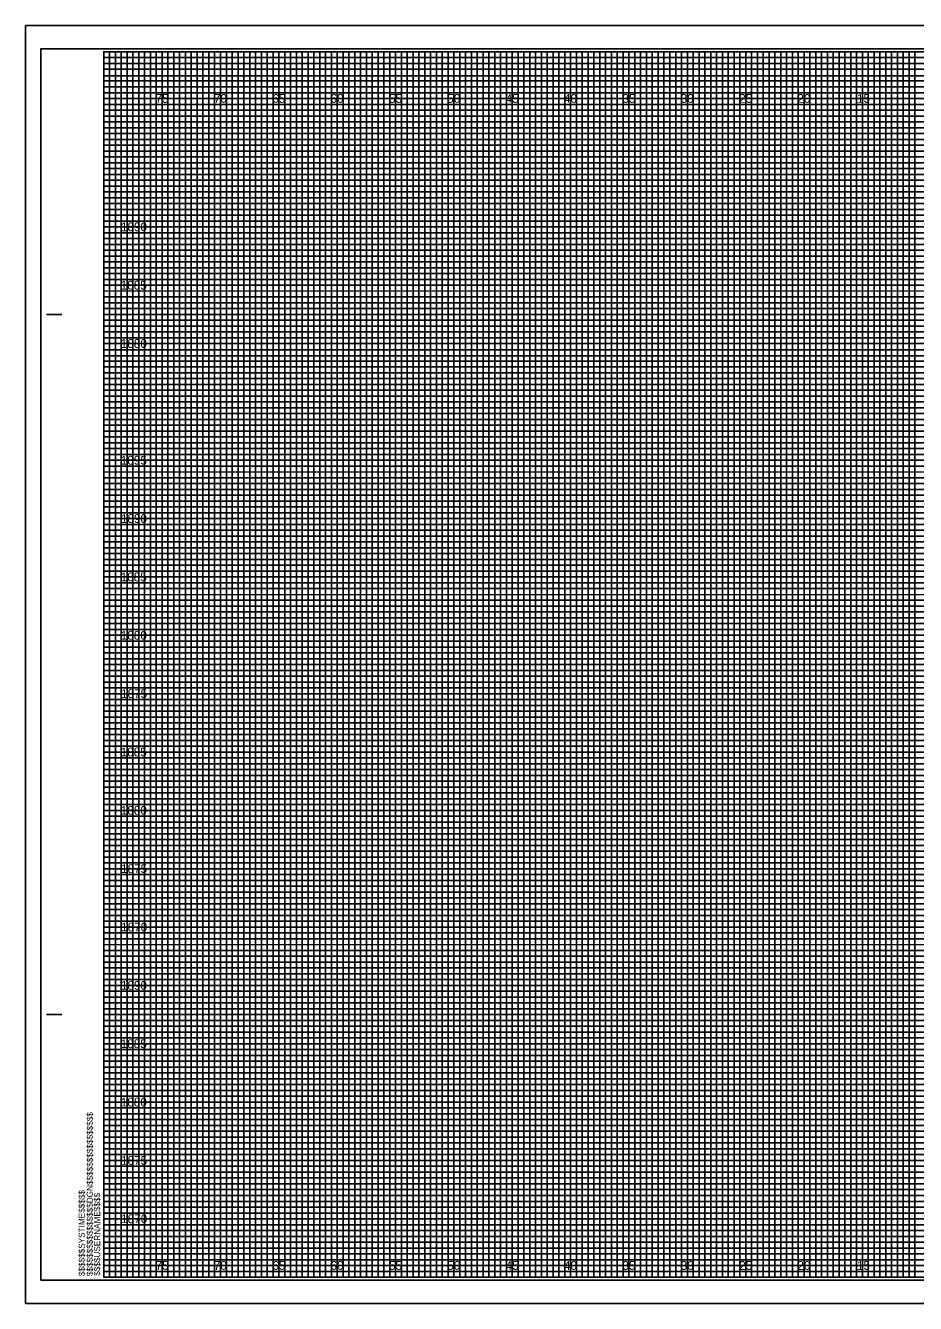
# Model space of a CAD drawing. Extents: x 3478 to 3647, y -9 to 100.
import ezdxf

# ---------------------------------------------------------------- set-up
doc = ezdxf.new("R2010")
doc.units = 0
for name, color, linetype in [('Scratch_Level_0', 7, 'Continuous'), ('Sheet Cross Section CELL', 7, 'Continuous'), ('Sheet Cross Section Grid Major CELL', 7, 'Continuous'), ('Sheet Cross Section Grid Middle CELL', 7, 'Continuous'), ('Sheet Cross Section Grid Minor 1 CELL', 7, 'Continuous'), ('Sheet Cross Section Grid Minor 2 CELL', 7, 'Continuous'), ('Sheet Cutting Line CELL', 7, 'Continuous'), ('Sheet DOT Grid CELL', 7, 'Continuous'), ('Sheet Plot Border Inside CELL', 7, 'Continuous'), ('Sheet Plot Border Outside CELL', 7, 'Continuous')]:
    doc.layers.add(name, color=color, linetype=linetype)

msp = doc.modelspace()

# ---------------------------------------------------------------- linework, layer by layer
at = {"layer": 'Sheet Cross Section CELL'}
for p, q in [((3480.11, 75.47), (3481.36, 75.47)), ((3480.16, 75.47), (3481.41, 75.47)), ((3480.11, 15.47), (3481.36, 15.47)), ((3480.16, 15.47), (3481.41, 15.47))]:
    msp.add_line(p, q, dxfattribs=at)
msp.add_lwpolyline([(3645.01, 97.97), (3485.01, 97.97), (3485.01, -7.03), (3645.01, -7.03)], close=True, dxfattribs=at)
at = {"layer": 'Sheet Cross Section Grid Major CELL'}
for p, q in [((3490.01, 97.97), (3485.01, 97.97)), ((3490.01, -7.03), (3490.01, 97.97)), ((3500.01, 97.97), (3495.01, 97.97)), ((3495.01, 97.97), (3495.01, -7.03)), ((3500.01, -7.03), (3500.01, 97.97)), ((3510.01, 97.97), (3505.01, 97.97)), ((3505.01, 97.97), (3505.01, -7.03)), ((3510.01, -7.03), (3510.01, 97.97)), ((3520.01, 97.97), (3515.01, 97.97)), ((3515.01, 97.97), (3515.01, -7.03)), ((3520.01, -7.03), (3520.01, 97.97)), ((3530.01, 97.97), (3525.01, 97.97)), ((3525.01, 97.97), (3525.01, -7.03)), ((3530.01, -7.03), (3530.01, 97.97)), ((3540.01, 97.97), (3535.01, 97.97)), ((3535.01, 97.97), (3535.01, -7.03)), ((3540.01, -7.03), (3540.01, 97.97)), ((3550.01, 97.97), (3545.01, 97.97)), ((3545.01, 97.97), (3545.01, -7.03)), ((3550.01, -7.03), (3550.01, 97.97)), ((3495.01, -7.03), (3490.01, -7.03)), ((3505.01, -7.03), (3500.01, -7.03)), ((3515.01, -7.03), (3510.01, -7.03)), ((3525.01, -7.03), (3520.01, -7.03)), ((3535.01, -7.03), (3530.01, -7.03)), ((3545.01, -7.03), (3540.01, -7.03)), ((3555.01, -7.03), (3550.01, -7.03))]:
    msp.add_line(p, q, dxfattribs=at)
for points in [[(3485.01, 92.97), (3645.01, 92.97), (3645.01, 87.97), (3485.01, 87.97)], [(3485.01, 82.97), (3645.01, 82.97), (3645.01, 77.97), (3485.01, 77.97)], [(3485.01, 72.97), (3645.01, 72.97), (3645.01, 67.97), (3485.01, 67.97)], [(3485.01, 62.97), (3645.01, 62.97), (3645.01, 57.97), (3485.01, 57.97)], [(3485.01, 52.97), (3645.01, 52.97), (3645.01, 47.97), (3485.01, 47.97)], [(3485.01, 42.97), (3645.01, 42.97), (3645.01, 37.97), (3485.01, 37.97)], [(3485.01, 32.97), (3645.01, 32.97), (3645.01, 27.97), (3485.01, 27.97)], [(3485.01, 22.97), (3645.01, 22.97), (3645.01, 17.97), (3485.01, 17.97)], [(3485.01, 12.97), (3645.01, 12.97), (3645.01, 7.97), (3485.01, 7.97)], [(3485.01, 2.97), (3645.01, 2.97), (3645.01, -2.03), (3485.01, -2.03)]]:
    msp.add_lwpolyline(points, dxfattribs=at)
at = {"layer": 'Sheet Cross Section Grid Middle CELL'}
for points in [[(3485.01, 97.97), (3487.51, 97.97), (3487.51, -7.03), (3492.51, -7.03), (3492.51, 97.97), (3497.51, 97.97), (3497.51, -7.03), (3502.51, -7.03), (3502.51, 97.97), (3507.51, 97.97), (3507.51, -7.03), (3512.51, -7.03), (3512.51, 97.97), (3517.51, 97.97), (3517.51, -7.03), (3522.51, -7.03), (3522.51, 97.97), (3527.51, 97.97), (3527.51, -7.03), (3532.51, -7.03), (3532.51, 97.97), (3537.51, 97.97), (3537.51, -7.03), (3542.51, -7.03), (3542.51, 97.97), (3547.51, 97.97), (3547.51, -7.03), (3552.51, -7.03), (3552.51, 97.97), (3557.51, 97.97)], [(3485.01, 95.47), (3622.51, 95.47)], [(3485.01, 85.47), (3645.01, 85.47), (3645.01, 90.47), (3485.01, 90.47)], [(3485.01, 75.47), (3645.01, 75.47), (3645.01, 80.47), (3485.01, 80.47)], [(3485.01, 65.47), (3645.01, 65.47), (3645.01, 70.47), (3485.01, 70.47)], [(3485.01, 55.47), (3645.01, 55.47), (3645.01, 60.47), (3485.01, 60.47)], [(3485.01, 45.47), (3645.01, 45.47), (3645.01, 50.47), (3485.01, 50.47)], [(3485.01, 35.47), (3645.01, 35.47), (3645.01, 40.47), (3485.01, 40.47)], [(3485.01, 25.47), (3645.01, 25.47), (3645.01, 30.47), (3485.01, 30.47)], [(3485.01, 15.47), (3645.01, 15.47), (3645.01, 20.47), (3485.01, 20.47)], [(3485.01, 5.47), (3645.01, 5.47), (3645.01, 10.47), (3485.01, 10.47)], [(3485.01, -4.53), (3645.01, -4.53), (3645.01, 0.47), (3485.01, 0.47)]]:
    msp.add_lwpolyline(points, dxfattribs=at)
at = {"layer": 'Sheet Cross Section Grid Minor 1 CELL'}
for p, q in [((3485.01, 97.47), (3615.01, 97.47)), ((3615.01, 96.96), (3485.01, 96.96)), ((3485.01, 96.96), (3485.01, 96.47)), ((3485.01, 96.47), (3615.01, 96.47)), ((3615.01, 95.92), (3485.01, 95.92)), ((3485.01, 95.92), (3485.01, 94.97)), ((3485.01, 94.97), (3645.01, 94.97))]:
    msp.add_line(p, q, dxfattribs=at)
for points in [[(3485.01, 94.47), (3620.01, 94.47), (3645.01, 94.47), (3645.01, 93.97), (3485.01, 93.97)], [(3485.01, 93.47), (3645.01, 93.47), (3645.01, 92.47), (3485.01, 92.47)], [(3485.01, 91.97), (3645.01, 91.97), (3645.01, 91.47), (3485.01, 91.46)], [(3485.01, 90.97), (3645.01, 90.97), (3645.01, 89.97), (3485.01, 89.97)], [(3485.01, 89.47), (3645.01, 89.47), (3645.01, 88.97), (3485.01, 88.97)], [(3485.01, 88.47), (3645.01, 88.47), (3645.01, 87.47), (3485.01, 87.47)], [(3485.01, 86.97), (3645.01, 86.97), (3645.01, 86.47), (3485.01, 86.47)], [(3485.01, 85.97), (3645.01, 85.97), (3645.01, 84.97), (3485.01, 84.97)], [(3485.01, 84.47), (3645.01, 84.47), (3645.01, 83.97), (3485.01, 83.97)], [(3485.01, 83.47), (3645.01, 83.47), (3645.01, 82.47), (3485.01, 82.47)], [(3485.01, 81.97), (3645.01, 81.97), (3645.01, 81.47), (3485.01, 81.47)], [(3485.01, 80.97), (3645.01, 80.97), (3645.01, 79.95), (3645.01, 79.47), (3645.01, 78.97), (3485.01, 78.97)], [(3485.01, 79.97), (3645.01, 79.97), (3645.01, 79.47), (3485.01, 79.47)], [(3485.01, 78.47), (3645.01, 78.47), (3645.01, 77.47), (3485.01, 77.49)], [(3485.01, 77.49), (3645.01, 77.47), (3645.01, 76.97), (3485.01, 76.97)], [(3485.01, 76.47), (3645.01, 76.47), (3645.01, 75.97), (3485.01, 75.97)], [(3485.01, 74.97), (3645.01, 74.97), (3645.01, 74.47), (3485.01, 74.47)], [(3485.01, 73.97), (3645.01, 73.97), (3645.01, 73.47), (3485.01, 73.47)], [(3484.97, 72.42), (3645.01, 72.42), (3645.01, 71.91), (3484.97, 71.91)], [(3485.01, 71.47), (3645.01, 71.47), (3645.01, 70.97), (3485.01, 70.97)], [(3485.01, 69.97), (3645.01, 69.97), (3645.01, 69.47), (3485.01, 69.47)], [(3485.01, 68.97), (3645.01, 68.97), (3645.01, 68.47), (3485.01, 68.47)], [(3485.01, 67.47), (3645.01, 67.47), (3645.01, 66.97), (3485.01, 66.97)], [(3485.01, 66.47), (3645.01, 66.47), (3645.01, 65.97), (3485.01, 65.97)], [(3485.01, 64.97), (3645.01, 64.97), (3645.01, 64.47), (3485.01, 64.47)], [(3485.01, 63.97), (3645.01, 63.97), (3645.01, 63.47), (3485.01, 63.47)], [(3485.01, 62.47), (3645.01, 62.47), (3645, 61.96), (3485.01, 61.97)], [(3485.01, 61.47), (3645.01, 61.47), (3645.01, 60.97), (3485.01, 60.97)], [(3485.01, 59.97), (3645.01, 59.97), (3645.01, 59.47), (3485.01, 59.47)], [(3485.01, 58.97), (3645.01, 58.97), (3645.01, 58.47), (3485.01, 58.47)], [(3485.01, 57.47), (3645.01, 57.47), (3645.01, 56.97), (3485.01, 56.97)], [(3485.01, 56.47), (3645.01, 56.47), (3645.01, 55.97), (3485.01, 55.97)], [(3485.01, 54.97), (3645.01, 54.97), (3645.01, 54.47), (3485.01, 54.47)], [(3485.01, 53.97), (3645.01, 53.97), (3645.01, 53.47), (3485.01, 53.47)], [(3485.01, 52.47), (3645.01, 52.47), (3645.01, 51.97), (3485.01, 51.97)], [(3485.01, 51.47), (3645.04, 51.43), (3645.01, 50.97), (3485.01, 50.97)], [(3485.01, 49.97), (3645.01, 49.97), (3645.01, 49.47), (3485.01, 49.47)], [(3485.01, 48.97), (3645.01, 48.97), (3645.01, 48.47), (3485.01, 48.47)], [(3485.01, 47.47), (3645.01, 47.47), (3645.01, 46.97), (3485.01, 46.97)], [(3485.01, 46.47), (3645.01, 46.47), (3645.01, 45.97), (3485.01, 45.97)], [(3485.01, 44.97), (3645.01, 44.97), (3645.01, 44.47), (3485.01, 44.47)], [(3485.01, 43.97), (3645.01, 43.97), (3645.01, 43.47), (3485.01, 43.47)], [(3485.01, 42.47), (3645.01, 42.47), (3645.01, 41.97), (3485.01, 41.97)], [(3485.01, 41.47), (3645.01, 41.47), (3645.01, 40.97), (3485.01, 40.97)], [(3485.01, 39.97), (3645.01, 39.97), (3645.01, 39.47), (3485.01, 39.47)], [(3485.01, 38.97), (3645.01, 38.97), (3645.01, 38.47), (3485.01, 38.47)], [(3485.01, 37.47), (3645.01, 37.47), (3645.01, 36.97), (3485.01, 36.97)], [(3485.01, 36.47), (3645.01, 36.47), (3645.01, 35.97), (3485.01, 35.97)], [(3485.01, 34.97), (3645.01, 34.97), (3645.01, 34.47), (3485.01, 34.47)], [(3485.01, 33.97), (3645.01, 33.97), (3645.01, 33.47), (3485.01, 33.47)], [(3485.01, 32.47), (3645.01, 32.47), (3645, 31.96), (3485.01, 31.97)], [(3485.01, 31.47), (3645.01, 31.47), (3645.01, 30.97), (3485.01, 30.97)], [(3485.01, 29.97), (3645.01, 29.97), (3645.01, 29.47), (3485.01, 29.47)], [(3485.01, 28.97), (3645.01, 28.97), (3645.01, 28.47), (3485.01, 28.47)], [(3485.01, 27.47), (3645.01, 27.47), (3645.01, 26.97), (3485.01, 26.97)], [(3485.01, 26.47), (3645.01, 26.47), (3645.01, 25.97), (3485.01, 25.97)], [(3485.01, 24.97), (3645.01, 24.97), (3645.01, 24.47), (3485.01, 24.47)], [(3485.01, 23.97), (3645.01, 23.97), (3645.01, 23.47), (3485.01, 23.47)], [(3485.01, 22.47), (3645.01, 22.47), (3645.01, 21.97), (3485.01, 21.97)], [(3485.01, 21.47), (3645.04, 21.43), (3645.01, 20.97), (3485.01, 20.97)], [(3485.01, 19.97), (3645.01, 19.97), (3645.01, 19.47), (3485.01, 19.47)], [(3485.01, 18.97), (3645.01, 18.97), (3645.01, 18.47), (3485.01, 18.47)], [(3485.01, 17.47), (3645.01, 17.47), (3645.01, 16.97), (3485.01, 16.97)], [(3485.01, 16.47), (3645.01, 16.47), (3645.01, 15.97), (3485.01, 15.97)], [(3485.01, 14.97), (3645.01, 14.97), (3645.01, 14.47), (3485.01, 14.47)], [(3485.01, 13.97), (3645.01, 13.97), (3645.01, 13.47), (3485.01, 13.47)], [(3485.01, 12.47), (3645.01, 12.47), (3645.01, 11.97), (3485.01, 11.97)], [(3485.01, 11.47), (3645.01, 11.47), (3645.01, 10.97), (3485.01, 10.97)], [(3485.01, 9.97), (3645.01, 9.97), (3645.01, 9.47), (3485.01, 9.47)], [(3485.01, 8.97), (3645.01, 8.97), (3645.01, 8.47), (3485.01, 8.47)], [(3485.01, 7.47), (3645.01, 7.47), (3645.01, 6.97), (3485.01, 6.97)], [(3485.01, 6.47), (3645.01, 6.47), (3645.01, 5.97), (3485.01, 5.97)], [(3485.01, 4.97), (3645.01, 4.97), (3645.01, 4.47), (3485.01, 4.47)], [(3485.01, 3.97), (3645.01, 3.97), (3645.01, 3.47), (3485.01, 3.47)], [(3485.01, 2.47), (3645.01, 2.47), (3645.01, 1.97), (3485.01, 1.97)], [(3485.01, 1.47), (3645.01, 1.47), (3645.01, 0.97), (3485.01, 0.97)], [(3485.01, -0.03), (3645.01, -0.03), (3645.01, -0.53), (3485.01, -0.53)], [(3485.01, -1.03), (3645.01, -1.03), (3645.01, -1.53), (3485.01, -1.53)], [(3485.01, -2.53), (3645.01, -2.53), (3645.01, -3.03), (3485.01, -3.03)], [(3485.01, -3.53), (3645.01, -3.53), (3645.01, -4.03), (3485.01, -4.03)], [(3485.01, -5.03), (3645.01, -5.03), (3645.01, -5.53), (3485.01, -5.53)], [(3485.01, -6.03), (3645.01, -6.03), (3645.01, -6.53), (3485.01, -6.53)]]:
    msp.add_lwpolyline(points, dxfattribs=at)
at = {"layer": 'Sheet Cross Section Grid Minor 2 CELL'}
for points in [[(3485.01, -7.03), (3485.51, -7.03), (3485.51, 97.97), (3486.01, 97.97), (3486.01, -7.03)], [(3486.01, -7.03), (3486.51, -7.03), (3486.51, 97.97), (3487.01, 97.97), (3487.01, -7.03)], [(3487.51, -7.03), (3488.01, -7.03), (3488.01, 97.97), (3488.51, 97.97), (3488.51, -7.03)], [(3488.51, -7.03), (3489.01, -7.03), (3489.01, 97.97), (3489.51, 97.97), (3489.51, -7.03)], [(3490.01, -7.03), (3490.51, -7.03), (3490.51, 97.97), (3491.01, 97.97), (3491.01, -7.03)], [(3491.01, -7.03), (3491.51, -7.03), (3491.51, 97.97), (3492.01, 97.97), (3492.01, -7.03)], [(3492.51, -7.03), (3493.01, -7.03), (3493.01, 97.97), (3493.51, 97.97), (3493.51, -7.03)], [(3493.51, -7.03), (3494.01, -7.03), (3494.01, 97.97), (3494.51, 97.97), (3494.51, -7.03)], [(3495.01, -7.03), (3495.51, -7.03), (3495.51, 97.97), (3496.01, 97.97), (3496.01, -7.03)], [(3496.01, -7.03), (3496.51, -7.03), (3496.51, 97.97), (3497.01, 97.97), (3497.01, -7.03)], [(3497.51, -7.03), (3498.01, -7.03), (3498.01, 97.97), (3498.51, 97.97), (3498.51, -7.03)], [(3498.51, -7.03), (3499.01, -7.03), (3499.01, 97.97), (3499.51, 97.97), (3499.51, -7.03)], [(3500.01, -7.03), (3500.51, -7.03), (3500.51, 97.97), (3501.01, 97.97), (3501.01, -7.03)], [(3501.01, -7.03), (3501.51, -7.03), (3501.51, 97.97), (3502.01, 97.97), (3502.01, -7.03)], [(3502.51, -7.03), (3503.01, -7.03), (3503.01, 97.97), (3503.51, 97.97), (3503.51, -7.03)], [(3503.51, -7.03), (3504.01, -7.03), (3504.01, 97.97), (3504.51, 97.97), (3504.51, -7.03)], [(3505.01, -7.03), (3505.51, -7.03), (3505.51, 97.97), (3506.01, 97.97), (3506.01, -7.03)], [(3506.01, -7.03), (3506.51, -7.03), (3506.51, 97.97), (3507.01, 97.97), (3507.01, -7.03)], [(3507.51, -7.03), (3508.01, -7.03), (3508.01, 97.97), (3508.51, 97.97), (3508.51, -7.03)], [(3508.51, -7.03), (3509.01, -7.03), (3509.01, 97.97), (3509.51, 97.97), (3509.51, -7.03)], [(3510.01, -7.03), (3510.51, -7.03), (3510.51, 97.97), (3511.01, 97.97), (3511.01, -7.03)], [(3511.01, -7.03), (3511.51, -7.03), (3511.51, 97.97), (3512.01, 97.97), (3512.01, -7.03)], [(3512.51, -7.03), (3513.01, -7.03), (3513.01, 97.97), (3513.51, 97.97), (3513.51, -7.03)], [(3513.51, -7.03), (3514.01, -7.03), (3514.01, 97.97), (3514.51, 97.97), (3514.51, -7.03)], [(3515.01, -7.03), (3515.51, -7.03), (3515.51, 97.97), (3516.01, 97.97), (3516.01, -7.03)], [(3516.01, -7.03), (3516.51, -7.03), (3516.51, 97.97), (3517.01, 97.97), (3517.01, -7.03)], [(3517.51, -7.03), (3518.01, -7.03), (3518.01, 97.97), (3518.51, 97.97), (3518.51, -7.03)], [(3518.51, -7.03), (3519.01, -7.03), (3519.01, 97.97), (3519.51, 97.97), (3519.51, -7.03)], [(3520.01, -7.03), (3520.51, -7.03), (3520.51, 97.97), (3521.01, 97.97), (3521.01, -7.03)], [(3521.01, -7.03), (3521.51, -7.03), (3521.51, 97.97), (3522.01, 97.97), (3522.01, -7.03)], [(3522.51, -7.03), (3523.01, -7.03), (3523.01, 97.97), (3523.51, 97.97), (3523.51, -7.03)], [(3523.51, -7.03), (3524.01, -7.03), (3524.01, 97.97), (3524.51, 97.97), (3524.51, -7.03)], [(3525.01, -7.03), (3525.51, -7.03), (3525.51, 97.97), (3526.01, 97.97), (3526.01, -7.03)], [(3526.01, -7.03), (3526.51, -7.03), (3526.51, 97.97), (3527.01, 97.97), (3527.01, -7.03)], [(3527.51, -7.03), (3528.01, -7.03), (3528.01, 97.97), (3528.51, 97.97), (3528.51, -7.03)], [(3528.51, -7.03), (3529.01, -7.03), (3529.01, 97.97), (3529.51, 97.97), (3529.51, -7.03)], [(3530.01, -7.03), (3530.51, -7.03), (3530.51, 97.97), (3531.01, 97.97), (3531.01, -7.03)], [(3531.01, -7.03), (3531.51, -7.03), (3531.51, 97.97), (3532.01, 97.97), (3532.01, -7.03)], [(3532.51, -7.03), (3533.01, -7.03), (3533.01, 97.97), (3533.51, 97.97), (3533.51, -7.03)], [(3533.51, -7.03), (3534.01, -7.03), (3534.01, 97.97), (3534.51, 97.97), (3534.51, -7.03)], [(3535.01, -7.03), (3535.51, -7.03), (3535.51, 97.97), (3536.01, 97.97), (3536.01, -7.03)], [(3536.01, -7.03), (3536.51, -7.03), (3536.51, 97.97), (3537.01, 97.97), (3537.01, -7.03)], [(3537.51, -7.03), (3538.01, -7.03), (3538.01, 97.97), (3538.51, 97.97), (3538.51, -7.03)], [(3538.51, -7.03), (3539.01, -7.03), (3539.01, 97.97), (3539.51, 97.97), (3539.51, -7.03)], [(3540.01, -7.03), (3540.51, -7.03), (3540.51, 97.97), (3541.01, 97.97), (3541.01, -7.03)], [(3541.01, -7.03), (3541.51, -7.03), (3541.51, 97.97), (3542.01, 97.97), (3542.01, -7.03)], [(3542.51, -7.03), (3543.01, -7.03), (3543.01, 97.97), (3543.51, 97.97), (3543.51, -7.03)], [(3543.51, -7.03), (3544.01, -7.03), (3544.01, 97.97), (3544.51, 97.97), (3544.51, -7.03)], [(3545.01, -7.03), (3545.51, -7.03), (3545.51, 97.97), (3546.01, 97.97), (3546.01, -7.03)], [(3546.01, -7.03), (3546.51, -7.03), (3546.51, 97.97), (3547.01, 97.97), (3547.01, -7.03)], [(3547.51, -7.03), (3548.01, -7.03), (3548.01, 97.97), (3548.51, 97.97), (3548.51, -7.03)], [(3548.51, -7.03), (3549.01, -7.03), (3549.01, 97.97), (3549.51, 97.97), (3549.51, -7.03)], [(3550.01, -7.03), (3550.51, -7.03), (3550.51, 97.97), (3551.01, 97.97), (3551.01, -7.03)], [(3551.01, -7.03), (3551.51, -7.03), (3551.51, 97.97), (3552.01, 97.97), (3552.01, -7.03)], [(3552.51, -7.03), (3553.01, -7.03), (3553.01, 97.97), (3553.51, 97.97), (3553.51, -7.03)], [(3553.51, -7.03), (3554.01, -7.03), (3554.01, 97.97), (3554.51, 97.97), (3554.51, -7.03)]]:
    msp.add_lwpolyline(points, dxfattribs=at)
at = {"layer": 'Sheet Cutting Line CELL'}
for p, q in [((3646.66, 100.22), (3478.31, 100.22)), ((3478.31, 100.22), (3478.31, -9.28)), ((3478.31, -9.28), (3646.66, -9.28))]:
    msp.add_line(p, q, dxfattribs=at)
at = {"layer": 'Sheet DOT Grid CELL'}
for p, q in [((3490.01, -7.03), (3490.01, 97.97)), ((3495.01, -7.03), (3495.01, 97.97)), ((3500.01, -7.03), (3500.01, 97.97)), ((3505.01, -7.03), (3505.01, 97.97)), ((3510.01, -7.03), (3510.01, 97.97)), ((3515.01, -7.03), (3515.01, 97.97)), ((3520.01, -7.03), (3520.01, 97.97)), ((3525.01, -7.03), (3525.01, 97.97)), ((3530.01, -7.03), (3530.01, 97.97)), ((3535.01, -7.03), (3535.01, 97.97)), ((3540.01, -7.03), (3540.01, 97.97)), ((3545.01, -7.03), (3545.01, 97.97)), ((3550.01, -7.03), (3550.01, 97.97)), ((3485.01, 92.97), (3645.01, 92.97)), ((3485.01, 87.97), (3645.01, 87.97)), ((3485.01, 82.97), (3645.01, 82.97)), ((3485.01, 77.97), (3645.01, 77.97)), ((3485.01, 72.97), (3645.01, 72.97)), ((3485.01, 67.97), (3645.01, 67.97)), ((3485.01, 62.97), (3645.01, 62.97)), ((3485.01, 57.97), (3645.01, 57.97)), ((3485.01, 52.97), (3645.01, 52.97)), ((3485.01, 47.97), (3645.01, 47.97)), ((3485.01, 42.97), (3645.01, 42.97)), ((3485.01, 37.97), (3645.01, 37.97)), ((3485.01, 32.97), (3645.01, 32.97)), ((3485.01, 27.97), (3645.01, 27.97)), ((3485.01, 22.97), (3645.01, 22.97)), ((3485.01, 17.97), (3645.01, 17.97)), ((3485.01, 12.97), (3645.01, 12.97)), ((3485.01, 7.97), (3645.01, 7.97)), ((3485.01, 2.97), (3645.01, 2.97)), ((3485.01, -2.03), (3645.01, -2.03))]:
    msp.add_line(p, q, dxfattribs=at)
at = {"layer": 'Sheet Plot Border Inside CELL'}
msp.add_lwpolyline([(3479.61, -7.28), (3646.21, -7.28), (3646.21, 98.22), (3479.61, 98.22)], close=True, dxfattribs=at)
at = {"layer": 'Sheet Plot Border Outside CELL'}
msp.add_lwpolyline([(3478.31, -9.28), (3646.66, -9.28), (3646.66, 100.22), (3478.31, 100.22)], close=True, dxfattribs=at)

# ---------------------------------------------------------------- texts
at = {"layer": 'Scratch_Level_0'}
for s, p in [('1890', (3486.48, 82.6)), ('1885', (3486.46, 77.6)), ('1880', (3486.47, 72.6)), ('1895', (3486.47, 62.6)), ('1890', (3486.48, 57.6)), ('1885', (3486.46, 52.6)), ('1880', (3486.47, 47.6)), ('1875', (3486.49, 42.6)), ('1885', (3486.46, 37.6)), ('1880', (3486.47, 32.6)), ('1875', (3486.49, 27.6)), ('1870', (3486.5, 22.6)), ('1890', (3486.48, 17.6)), ('1885', (3486.46, 12.6)), ('1880', (3486.47, 7.6)), ('1875', (3486.49, 2.6)), ('1870', (3486.5, -2.4))]:
    msp.add_text(s, height=0.75, dxfattribs=at).set_placement(p)
at = {"layer": 'Sheet Cross Section CELL'}
for s, p in [('$$$$$$$$$$$$$$$$DGN$$$$$$$$$$$$$$$$', (3484.07, -6.94)), ('$$$$$$SYSTIME$$$$$', (3483.38, -6.94)), ('$$$$USERNAME$$$$', (3484.7, -6.91))]:
    msp.add_text(s, height=0.525, rotation=90, dxfattribs=at).set_placement(p)
at = {"layer": 'Sheet Plot Border Outside CELL'}
for s, p in [('75', (3489.45, 93.6)), ('70', (3494.44, 93.6)), ('65', (3499.45, 93.6)), ('60', (3504.44, 93.6)), ('55', (3509.45, 93.6)), ('50', (3514.44, 93.6)), ('45', (3519.45, 93.6)), ('40', (3524.44, 93.6)), ('35', (3529.45, 93.6)), ('30', (3534.44, 93.6)), ('25', (3539.45, 93.6)), ('20', (3544.44, 93.6)), ('15', (3549.54, 93.6)), ('75', (3489.45, -6.4)), ('70', (3494.44, -6.4)), ('65', (3499.45, -6.4)), ('60', (3504.44, -6.4)), ('55', (3509.45, -6.4)), ('50', (3514.44, -6.4)), ('45', (3519.45, -6.4)), ('40', (3524.44, -6.4)), ('35', (3529.45, -6.4)), ('30', (3534.44, -6.4)), ('25', (3539.45, -6.4)), ('20', (3544.44, -6.4)), ('15', (3549.54, -6.4))]:
    msp.add_text(s, height=0.75, dxfattribs=at).set_placement(p)

doc.saveas('drawing.dxf')
